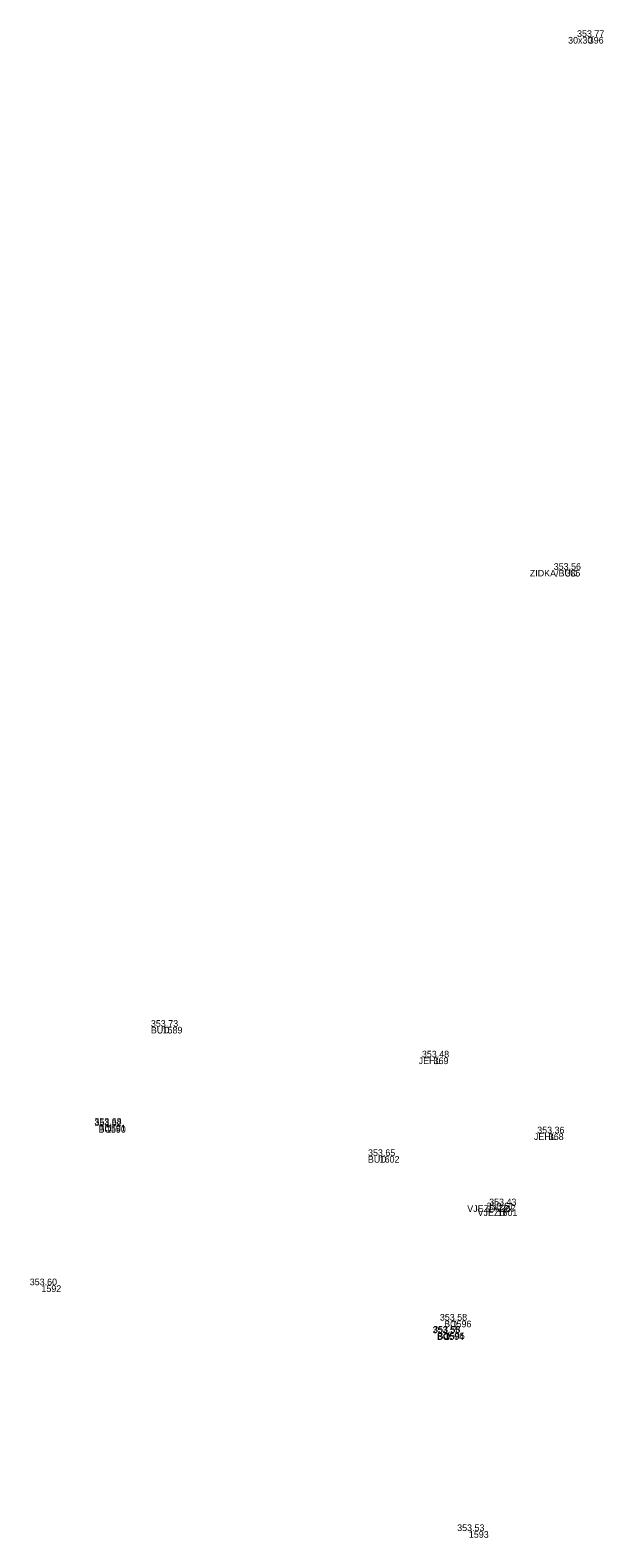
# Model space of a CAD drawing. Extents: x -590413 to -590216, y -1129419 to -1129249.
# Drawn here: x -590397.79 to -590389.17, y -1129355.18 to -1129332.55 of the extents above; entities that cross this region are included whole.
import ezdxf

# ---------------------------------------------------------------- set-up
doc = ezdxf.new("R2010")
doc.units = 0
for name, color, linetype in [('Vrstva B24', 7, 'Continuous'), ('Vrstva B58', 7, 'Continuous'), ('Vrstva B59', 7, 'Continuous'), ('Vrstva B60', 7, 'Continuous')]:
    doc.layers.add(name, color=color, linetype=linetype)

msp = doc.modelspace()

# ---------------------------------------------------------------- linework, layer by layer
at = {"layer": 'Vrstva B60'}
for p, q in [((-590389.4, -1129332.65), (-590389.4, -1129332.65)), ((-590389.75, -1129340.65), (-590389.75, -1129340.65)), ((-590395.8, -1129347.51), (-590395.8, -1129347.51)), ((-590391.73, -1129347.97), (-590391.73, -1129347.97)), ((-590396.65, -1129348.98), (-590396.65, -1129348.98)), ((-590396.65, -1129349), (-590396.65, -1129349)), ((-590390, -1129349.11), (-590390, -1129349.11)), ((-590392.54, -1129349.45), (-590392.54, -1129349.45)), ((-590390.77, -1129350.25), (-590390.77, -1129350.25)), ((-590390.72, -1129350.19), (-590390.72, -1129350.19)), ((-590397.62, -1129351.39), (-590397.62, -1129351.39)), ((-590391.56, -1129352.1), (-590391.56, -1129352.1)), ((-590391.46, -1129351.92), (-590391.46, -1129351.92)), ((-590391.57, -1129352.11), (-590391.57, -1129352.11)), ((-590391.2, -1129355.08), (-590391.2, -1129355.08))]:
    msp.add_line(p, q, dxfattribs=at)

# ---------------------------------------------------------------- texts
at = {"layer": 'Vrstva B24'}
for s, p in [('30x30', (-590389.71, -1129332.75)), ('ZIDKA/BUD', (-590390.285, -1129340.75)), ('BUD', (-590395.977, -1129347.61)), ('JEHL', (-590391.954, -1129348.07)), ('BO', (-590396.762, -1129349.08)), ('BO', (-590396.762, -1129349.1)), ('JEHL', (-590390.224, -1129349.21)), ('BUD', (-590392.717, -1129349.55)), ('VJEZD/ZO', (-590391.225, -1129350.29)), ('VJEZD', (-590391.07, -1129350.35)), ('BO', (-590391.672, -1129352.2)), ('BO', (-590391.572, -1129352.02)), ('BO', (-590391.682, -1129352.21))]:
    msp.add_text(s, height=0.1, dxfattribs=at).set_placement(p)
at = {"layer": 'Vrstva B58'}
for s, p in [('353.77', (-590389.576, -1129332.65)), ('353.56', (-590389.926, -1129340.65)), ('353.73', (-590395.976, -1129347.51)), ('353.48', (-590391.906, -1129347.97)), ('353.68', (-590396.825, -1129348.98)), ('353.62', (-590396.825, -1129349)), ('353.36', (-590390.174, -1129349.11)), ('353.65', (-590392.715, -1129349.45)), ('353.61', (-590390.933, -1129350.25)), ('353.43', (-590390.896, -1129350.19)), ('353.60', (-590397.795, -1129351.39)), ('353.58', (-590391.636, -1129351.92)), ('353.55', (-590391.746, -1129352.11)), ('353.58', (-590391.736, -1129352.1)), ('353.53', (-590391.376, -1129355.08))]:
    msp.add_text(s, height=0.1, dxfattribs=at).set_placement(p)
at = {"layer": 'Vrstva B59'}
for s, p in [('396', (-590389.4, -1129332.75)), ('385', (-590389.75, -1129340.75)), ('1589', (-590395.8, -1129347.61)), ('369', (-590391.73, -1129348.07)), ('1591', (-590396.65, -1129349.08)), ('1590', (-590396.65, -1129349.1)), ('368', (-590390, -1129349.21)), ('1602', (-590392.54, -1129349.55)), ('1601', (-590390.77, -1129350.35)), ('367', (-590390.72, -1129350.29)), ('1592', (-590397.62, -1129351.49)), ('1595', (-590391.56, -1129352.2)), ('1596', (-590391.46, -1129352.02)), ('1594', (-590391.57, -1129352.21)), ('1593', (-590391.2, -1129355.18))]:
    msp.add_text(s, height=0.1, dxfattribs=at).set_placement(p)

doc.saveas('drawing.dxf')
